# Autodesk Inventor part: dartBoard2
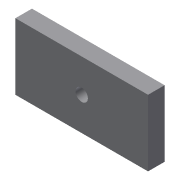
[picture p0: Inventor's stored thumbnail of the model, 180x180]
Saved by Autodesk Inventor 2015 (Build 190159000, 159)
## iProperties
Created: 2016-08
Part Number: dartBoard2
Material: Generic
Document SubType Name: Modeling
Designer: user
Density: 1 g/cm^3
Appearance: Default
Author: user
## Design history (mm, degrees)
sketch "Sketch1"
  geometry: L1 (-25.4, -12.7)-(25.4, -12.7); L2 (25.4, -12.7)-(25.4, 12.7); L3 (25.4, 12.7)-(-25.4, 12.7); L4 (-25.4, 12.7)-(-25.4, -12.7); L5 (-25.4, -12.7)-(25.4, 12.7); L6 (25.4, -12.7)-(-25.4, 12.7); C1 r 2.381 at (0, 0); 1 further point
  constraints: 12 end point, 2 midpoint, 2 parallel, 1 centre point, 1 coincident, 1 horizontal, 1 perpendicular
  dimensions: "d0" = 50.8 distance of L3.end L2.end; "d1" = 25.4 distance of L2.end L1.end; "d2" = 4.7625 diameter of C1
extrude "Extrusion1" new body sketch "Sketch1" distance "d3" = 6.35; taper "d4" = 0 deg
body "Solid1"
